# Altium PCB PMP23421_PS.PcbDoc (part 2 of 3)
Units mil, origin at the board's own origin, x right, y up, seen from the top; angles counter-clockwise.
Board outline 1978.53 x 2528.22 mil, 6 copper layers (Top Layer, Signal Layer 1, Signal Layer 2, Signal Layer 3, Signal Layer 4, Bottom Layer), stack 61.3 mil thick; 156 components, 45 nets, 410 pads, 635 vias.
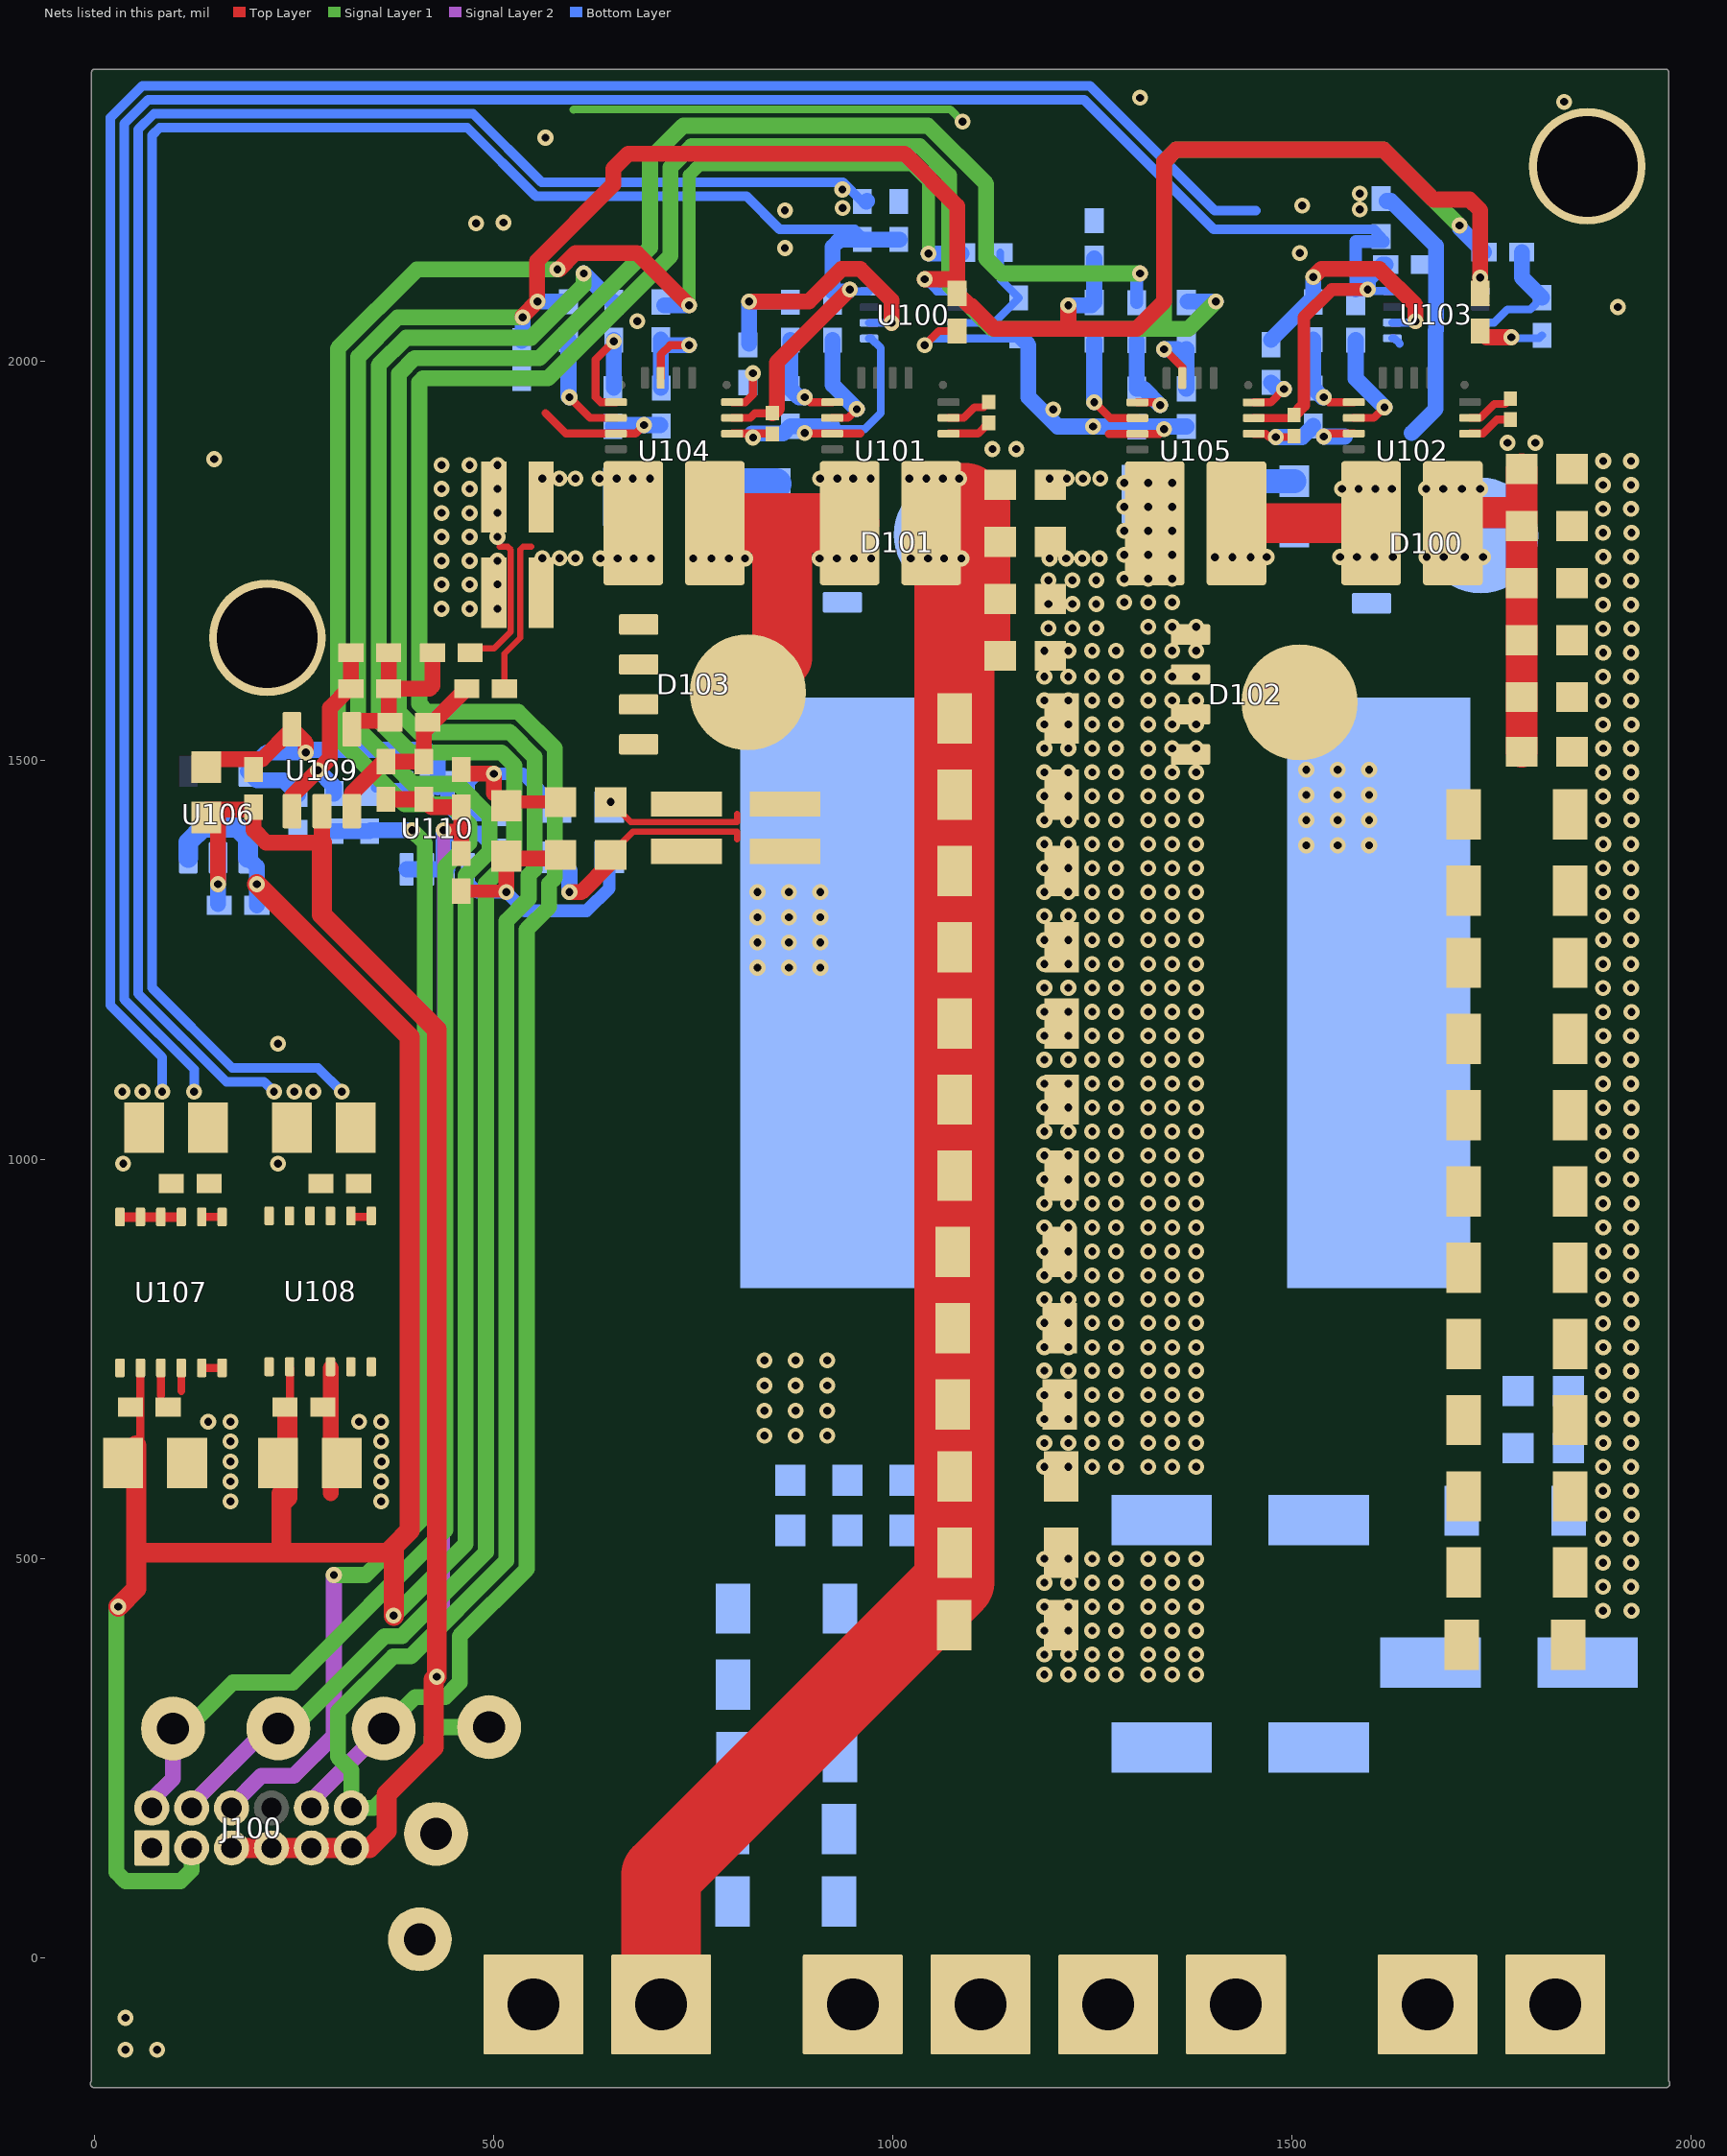
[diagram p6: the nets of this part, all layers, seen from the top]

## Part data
C100 C101 C102 C103 C104 C105 C122 C123 C124 C125 C126 C127 C128 C148 C149 C150 C151 C152 C153 C154 C155 C156 C157 C158 C159 C160 C161 C162 C163 C164 C165: library part C3216X6S1H475K160AB, "CAP CER 4.7UF 100V X7S 1206", Cap_Case=1206, TempCo=X7S, Tolerance_%=10, Value2=100V, ValueDisplayed=4.7µF
C106 C107 C108 C109 C110 C111 C112 C113 C114 C115 C116 C117 C118 C119 C120 C121: library part CMP-0077894-3, "CAP, CERM, 0.22 µF, 100 V,+/- 10%, X7S, AEC-Q200 Grade 1, 0603", Cap_Case=0603, Manufacturer="Taiyo Yuden", Supplier Part Number 1=963-MBASH168SC7224KT, TempCo=X7S, Tolerance_%=10%, Value2=100V, ValueDisplayed=0.22µF
C129 C130 C137 C138 C182 C183: "CAP, CERM, 0.1 µF, 16 V,+/- 10%, X7R, 0402", Cap_Case=0402, Manufacturer=AVX, Supplier Part Number 1=478-7888-1-ND, TempCo=X7R, Tolerance_%=10, Value2=16V, ValueDisplayed=0.1µF
C131 C132 C133 C134 C139 C140 C141 C142: "CAP, CERM, 10pF, 50V, +/-5%, C0G/NP0, 0402", Cap_Case=0402, Manufacturer=MuRata, Supplier Part Number 1=81-GRM1555C1H100JA1D, TempCo=C0G/NP0, Tolerance_%=5, Value1=Unknown, Value2=50V, ValueDisplayed=10pF
C135 C136 C143 C144: library part CMP-0009719-2, "CAP, CERM, 0.1 uF, 25 V, +/- 10%, X5R, 0201", Cap_Case=0201, Manufacturer=MuRata, Supplier Part Number 1=GRM033R61E104KE14D-ND, TempCo=X5R, Tolerance_%=10%, Value1=Unknown, Value2=25V, ValueDisplayed=0.1uF
C145 C146 C147: library part EEE-FK1H220P, "CAP ALUM POLY HYB 22UF 63V SMD", Cap_Case=D, Manufacturer=Rubycon, Tolerance_%=20, Value1="0.88 ohm", Value2=63V, ValueDisplayed=22µF
C166 C167: library part CMP-0006623-2, "CAP, CERM, 0.1 uF, 6.3 V, +/- 10%, X7R, 0402", Cap_Case=0402, Manufacturer=MuRata, Supplier Part Number 1=GRM155R70J104KA01D-ND, TempCo=X7R, Tolerance_%=10%, Value1=Unknown, Value2=6.3V, ValueDisplayed=0.1uF
C168 C176 C192: library part CMP-0064911-2, "CAP, CERM, 10 pF, 50 V,+/- 2.5%, C0G/NP0, AEC-Q200 Grade 1, 0402", Cap_Case=0402, Manufacturer=AVX, Supplier Part Number 1=478-5991-1-ND, TempCo=C0G/NP0, Tolerance_%=2.5%, Value1=Unknown, Value2=50V, ValueDisplayed=10pF
C169 C177: "CAP, CERM, 10 µF, 16 V,+/- 10%, X7S, 0805", Cap_Case=0805, Manufacturer=MuRata, Supplier Part Number 1=490-12756-1-ND, TempCo=X7S, Tolerance_%=10, Value2=16V, ValueDisplayed=10µF
C170 C171 C173 C179: library part 0402ZC103KAT2A, "CAP CER 0.015UF 25V X7R 0402", Cap_Case=0402, Manufacturer=AVX, Supplier Part Number 1=490-17756-1-ND, TempCo=X7R, Tolerance_%=10, Value2=25V, ValueDisplayed=0.015µF
C172 C189: "CAP, CERM, 0.01 µF, 10 V,+/- 10%, X7R, 0402", Cap_Case=0402, Manufacturer=AVX, Supplier Part Number 1=478-7890-1-ND, TempCo=X7R, Tolerance_%=10, Value2=10V, ValueDisplayed=0.01µF
C174 C191: library part CMP-0008377-2, "CAP, CERM, 22 uF, 10 V, +/- 20%, X7R, 0805", Cap_Case=0805, Manufacturer=MuRata, Supplier Part Number 1=81-GRM21BZ71A226ME5L, TempCo=X7R, Tolerance_%=20%, Value1=Unknown, Value2=10V, ValueDisplayed=22uF
C175: library part CMP-0080610-1, "CAP, CERM, 0.1 µF, 25 V,+/- 10%, X7R, AEC-Q200 Grade 1, 0402", Cap_Case=0402, Manufacturer=TDK, Supplier Part Number 1=445-6902-1-ND, TempCo=X7R, Tolerance_%=10%, Value2=25V, ValueDisplayed=0.1µF
C180 C181: library part CMP-0007473-4, "CAP, CERM, 1800 pF, 100 V, +/- 10%, X7R, 0603", Cap_Case=0603, Manufacturer=MuRata, Supplier Part Number 1=490-1477-1-ND, TempCo=X7R, Tolerance_%=10%, Value1=Unknown, Value2=100V, ValueDisplayed=1800pF
C184: "CAP, CERM, 68 pF, 50 V,+/- 5%, C0G/NP0, 0603", Cap_Case=0603, Manufacturer=AVX, Supplier Part Number 1=478-1173-1-ND, TempCo=C0G/NP0, Tolerance_%=5, Value1="0.144 ohm", Value2=50V, ValueDisplayed=68pF
C185 C186: "CAP, CERM, 47 pF, 50 V,+/- 1%, C0G/NP0, 0402", Cap_Case=0402, Manufacturer=MuRata, Supplier Part Number 1=490-6241-1-ND, TempCo=C0G/NP0, Tolerance_%=1, Value2=50V, ValueDisplayed=47pF
C187: "CAP, CERM, 1 µF, 16 V,+/- 10%, X7R, 0603", Cap_Case=0603, Manufacturer=TDK, Supplier Part Number 1=445-1604-1-ND, TempCo=X7R, Tolerance_%=10, Value1="0.0057 ohm", Value2=16V, ValueDisplayed=1µF
C188: "CAP, CERM, 0.1uF, 6.3V, +/-10%, X7R, 0402", Cap_Case=0402, Manufacturer=MuRata, Supplier Part Number 1=GRM155R70J104KA01D-ND, TempCo=X7R, Tolerance_%=10, Value1=Unknown, Value2=6.3V, ValueDisplayed=0.1uF
D100 D101 D102 D103: library part CMP-0032275-1, "Diode 100 V 30A Surface Mount PowerFlat™ (5x6)", Digikey Part Number=497-10342-1-ND, Forward Current=30A, Manufacturer=STMicroelectronics, Max Surge Forward Current=200A, Mouser Part Number=511-STPS30M100DJF-TR, Operating Temperature Range="to +150°C", Peak Reverse Current=100uA
J100: library part CMP-0093439-1, "Connector Header Through Hole, Right Angle 12 position 0.050\" (1.27mm)", Current_A=1A, Digikey Part Number=952-1396-ND, Manufacturer=Harwin, Mouser Part Number=855-M50-3900642, Operating Temperature Range="-40°C to +105°C"
L100: library part CMP-0063542-1, "Inductor, Shielded, 2.2 uH, 48 A, 0.00123 ohm, AEC-Q200 Grade 0, SMD", Manufacturer=Vishay-Dale, Supplier Part Number 1=52X6073, Value1="0.00123 ohm", Value2=48A, ValueDisplayed=2.2uH
LOGO100: library part CMP-0074837-1, "IEC 61010-1 Hot Surface Warning"
Logo101: library part Pb-Free
Logo102: library part CMP-0074769-1
Logo103: library part CMP-0074847-1, "FCC_disclaimer"
R100 R101 R111 R112: "RES, 3.01, 1%, 0.063 W, 0402", Manufacturer=Vishay-Dale, Power_W=0.063, Supplier Part Number 1=541-3.01LLCT-ND, TempCo="100 ppm/C", Tolerance_%=1, Value1=1%, Value2=0.063W, Value_Code=3R01, ValueDisplayed=3.01
R102 R103 R119 R123: library part CMP-0015357-3, "RES, 0.002, 2%, 1 W, 0508", Manufacturer="Susumu Co Ltd", Power_W=1W, Supplier Part Number 1=408-1592-1-ND, TempCo="100 ppm/C", Tolerance_%=2%, Value_Code=2L000, ValueDisplayed=0.002
R104 R105 R106 R107 R108 R109 R113 R114 R117 R118 R124 R128: "RES, 0, 5%, 0.063 W, 0402", Manufacturer=Vishay-Dale, Power_W=0.063, Supplier Part Number 1=541-0.0JCT-ND, TempCo="200 ppm/C", Tolerance_%=5, Value1=5%, Value2=0.063W, Value_Code=0000, ValueDisplayed=0
R110 R120 R121 R122: "RES, 100, 1%, 0.1 W, 0603", Manufacturer="Yageo America", Power_W=0.1, Supplier Part Number 1=311-100HRCT-ND, TempCo="200 ppm/C", Tolerance_%=1, Value1=1%, Value2=0.1W, Value_Code=100R, ValueDisplayed=100
R115 R116: library part CMP-0016888-3, "RES, 2.55, 1%, 0.25 W, AEC-Q200 Grade 0, 1206", Manufacturer=Vishay-Dale, Power_W=250mW, Supplier Part Number 1=541-2.55FFCT-ND, TempCo="100 ppm/C", Tolerance_%=1%, Value2=0.25W, Value_Code=2R55, ValueDisplayed=2.55
R127 R129: "RES, 33.2 k, 1%, 0.063 W, 0402", Manufacturer=Vishay-Dale, Power_W=0.063, Supplier Part Number 1=541-33.2KLCT-ND, TempCo="100 ppm/C", Tolerance_%=1, Value1=1%, Value2=0.063W, Value_Code=33k2, ValueDisplayed=33.2k
R327 R328: library part CMP-0026071-3, "RES, 1.00 k, 1%, 0.063 W, AEC-Q200 Grade 0, 0402", Manufacturer=Vishay-Dale, Power_W=63mW, Supplier Part Number 1=541-1.00KLCT-ND, TempCo="100 ppm/C", Tolerance_%=1%, Value2=0.063W, Value_Code=1k00, ValueDisplayed=1.00k
TP100 TP101 TP102 TP103: "Test Point, Miniature, Orange, TH", Color=Orange, Manufacturer=Keystone, Supplier Part Number 1=36-5003-ND
TP104 TP105: "Test Point, Miniature, Black, TH", Color=Black, Manufacturer=Keystone, Supplier Part Number 1=36-5001-ND
U100 U103: library part CMP-0035039-1, "General Purpose Dual-Channel Functional Isolators", Manufacturer="Texas Instruments", Max Supply Voltage=5.5V, Min Supply Voltage=1.71V, Nominal Supply Current=1.2-5.2mA, Operating Temperature Range="-40°C to +125°C"
U101 U102 U104 U105: library part CMP-0037654-1, "100-V, 64-A GaN with Integrated Driver", Manufacturer="Texas Instruments", Max Supply Voltage=5.25V, Min Supply Voltage=4.75V, Nominal Supply Current=3mA, Operating Temperature Range="-40°C to +125°C"
U106: library part CMP-0066771-1, "150-mA, Low-Dropout Regulator with Foldback Current Limit for Portable Devices, DBV0005A (SOT-23-5)", Alternate Manufacturer="Texas Instruments", Alternate PartNumber=TLV71333PDBVT
U107 U108: library part CMP-0098322-4, "1.5W, High-Density, >3 kVRMS Isolated DC-DC Converter", Manufacturer="Texas Instruments", Max Supply Voltage=5.5V, Min Supply Voltage=4.5V, Operating Temperature Range=to, Output Voltage=5V
U109: library part CMP-0032028-2, "CMOS Amplifier 1 Circuit Rail-to-Rail SOT-23-5", Digikey Part Number=296-TLV365DBVRQ1-ND, Input Bias Current=0.000005uA, Input Offset Voltage=0.4mV, Manufacturer="Texas Instruments", Max Supply Voltage=5.5V, Min Supply Voltage=2.2V, Mouser Part Number=595-TLV365DBVRQ1, Nominal Supply Current=4.6mA, Operating Temperature Range="-40°C to +125°C", Output Current Per Channel=85mA, Voltage Gain=120dB
U110: library part CMP-0093654-2, "-4-V to 110-V, Bidirectional, 1-MHz, 5V/µs, Ultra-Precise Current Sense Amplifier, SOT23-8", Input Bias Current=40uA, Input Offset Voltage=0.002mV, Manufacturer="Texas Instruments", Max Supply Voltage=20V, Min Supply Voltage=2.7V, Nominal Supply Current=2.5mA, Operating Temperature Range="-40°C to +125°C", Voltage Gain=0.05V/mV
VBAT100 VBAT101 VBAT-100 VBAT-101 VBAT-102 VBAT-103 VOUT100 VOUT101: library part CMP-0055044-1, "PCB Pin, 0.04\" DIA, Edge-Mount", Manufacturer=Mill-Max, Supplier Part Number 1=ED1278-ND

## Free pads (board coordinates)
  round 146 hole 125.98: 1(216.54,1653.54) 1(1870.08,2244.09)

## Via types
v1: diameter 20, hole 10, Top Layer to Bottom Layer, 627 vias
v2: diameter 20, hole 10, Top Layer to Bottom Layer, tented both sides, 8 vias

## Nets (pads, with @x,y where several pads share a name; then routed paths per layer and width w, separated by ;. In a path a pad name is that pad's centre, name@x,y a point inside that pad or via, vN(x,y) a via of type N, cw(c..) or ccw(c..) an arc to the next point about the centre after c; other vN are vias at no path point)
3V3: C166.1 C175.1 C187.1 C188.1 U106.5 U109.5 U110.6 U110.7 | length 634
  Top Layer w20: C187.1@140,1501.5 210.16,1501.5 U109.5@247.6,1538.94 265,1521.54 v1(265,1510)
  Bottom Layer w16: 430,1466.01 U110.7@442.33,1466.01 442.33,1443.17 453.66,1431.84 C188.1@514.3,1431.84
  Bottom Layer w20: C166.1@255,1457.24 237.24,1475 203.78,1475 U106.5@192.4,1486.38 216.02,1510 v1(265,1510) 268.26,1513.26 416.74,1513.26 430,1500 430,1466.01
5V: C137.1 C138.1 C167.1 C169.1 C171.1 C177.1 C179.1 C182.1 C183.1 J100.3 R111.1 R112.1 U100.1 U103.1 U106.1 U106.3 U107.1 U107.2 U108.1 U108.2 | length 6582.2
  Top Layer w10: C177.1@57.68,641.9 U107.2@57.68,739.13 ; 245.08,676.38 U108.2@245.08,739.13
  Top Layer w20: v1(536.52,2055) 536.52,2056.52 v1(555,2075) 554.5,2075.5 554.5,2125.56 650,2221.06 650,2241 669,2260 1015,2260 1080.72,2194.28 1080.72,2105 ; v1(1040,2102.71) 1078.43,2102.71 1080.72,2105 ; 1220,2044 v1(1220,2070.06) ; C183.1@1736.05,2085.06 1736.05,2188.95 1722.5,2202.5 1677.5,2202.5 1615,2265 1355,2265 1340,2250 1340,2075 1305.5,2040.5 1127.51,2040.5 1098.95,2069.06 1096.71,2069.06 C182.1@1080.72,2085.06 1080.72,2105
  Top Layer w25: v1(30,440) 52.51,462.51 C177.1@52.51,641.9 ; 60.21,507.7 367.3,507.7 375,515.4 ; v1(203.62,1345) 395,1153.62 395,535.4 375,515.4 ; 234.12,520.88 234.12,569.12 ; 234.12,581.61 234.12,569.12 ; 241.73,676.38 241.73,576.73 234.12,569.12 ; v1(375,428.7) 375,515.4
  Signal Layer 1 w20: v1(30,440) 27.56,437.56 27.56,107.44 38.75,96.25 108.06,96.25 121.85,110.04 J100.3@121.85,137.8 ; v1(375,428.7) 465.07,518.78 465.07,1356.12 495,1386.05 495,1430.56 455.06,1470.5 399.09,1470.5 330.54,1539.05 330.54,2005.53 380.01,2055 v1(536.52,2055)
  Bottom Layer w10: v1(1040,2102.71) 1055.19,2087.52 U100.1@1080.72,2087.52 ; U103.1@1736.05,2087.85 v1@1736.05,2109.43
  Bottom Layer w20: U106.1@192.4,1378.11 203.62,1366.89 v1(203.62,1345) C167.1@203.62,1318.62 ; C137.1@535.09,2025.54 536.52,2026.98 v1(536.52,2055) ; v1(555,2075) R111.1@593.31,2075 ; v1(1220,2070.06) R112.1@1248.95,2070.06 ; R112.1@1252.44,2073.54 C138.1@1252.44,2128.99
  Bottom Layer w25: U106.3@117.6,1378.11 117.6,1397.6 135.8,1415.8 179.2,1415.8 192.4,1402.6 U106.1@192.4,1378.11
  other v1: 1736.05,2105
12V: J100.1 | length 1.8
  Signal Layer 1 w20: J100.1@70.87,136.81 J100.1@71.85,137.8
  Bottom Layer w12: J100.1@71.85,137.8 J100.1@71.85,138.23
48VOUT1: C114.1 C115.1 C116.1 C117.1 C118.1 C119.1 C120.1 C121.1 C122.1 C123.1 C124.1 C125.1 C126.1 C127.1 C128.1 C145.1 C146.1 C147.1 C160.1 C161.1 C162.1 C163.1 C164.1 C165.1 D100.5 U102.7 VOUT100.1 VOUT101.1 | length 423.7
  Top Layer w39.37: U102.7@1701.64,1810.45 C119.1@1771.06,1810.45 ; C115.1@1787.93,1510.75 C117.1@1787.93,1579.15 C121.1@1787.93,1650.63 C120.1@1787.93,1722.11 C119.1@1787.93,1793.58 C118.1@1787.93,1865.06
  other v1: 1668.83,1754.85 1690.19,1754.85 1716.66,1754.85 1739.43,1754.85 1668.27,1840.08 1689.85,1840.08 1712.99,1840.08 1736,1840.08 1770,1897.79 1805,1897.79
CSA: C129.2 C132.2 C143.2 C173.2 C180.1 C189.2 C191.2 D101.1 D101.2 D101.3 D101.4 D103.5 R102.1 R103.1 R120.2 R121.2 U100.5 U101.4 U101.6 U104.7 U104.8 U108.9 U108.10 U108.11 U108.12 | length 3175.6
  Top Layer w7.87: v1(646.83,1447.93) 671.7,1423 804.86,1423 804.86,1432.88
  Top Layer w10: U104.8@798.96,1909.37 C143.2@848.88,1909.37 ; v1@890.63,1909.37 U101.4@924.29,1909.37 959.54,1909.37
  Top Layer w75: U104.7@777.3,1797.17 861.62,1797.17 ; D103.5@861.62,1628.37 861.62,1797.17 ; U101.6@945.94,1797.17 861.62,1797.17
  Bottom Layer w10: 924.66,1918.59 928.25,1915 965,1915 985,1935 985,2016.66 973.19,2028.47 U100.5@970.48,2028.47
  Bottom Layer w12: v1(225,1085) 212.5,1097.5 165.25,1097.5 55,1207.75 55,2290.5 74.7,2310.2 474.25,2310.2 560.03,2224.43 937.32,2224.43 C189.2@961.8,2199.94
  Bottom Layer w20: v1@823.92,1909.37 862.44,1909.37 C132.2@871.65,1918.59 924.66,1918.59 ; C189.2@967.11,2200 C189.2@967.89,2200.79
  other v1: 230,995 250.29,1085 274.26,1085 772.98,1753 815.1,1753 908.52,1753 951.49,1753 909.06,1853 930.55,1853 950.71,1853 972.36,1853 825.15,1904.42 890,1910 865,2141.77 865,2188.98 937.32,2191.85 937.01,2215.07
  other v2: 750.14,1753 795.02,1753 930.2,1753 973.11,1753
CSB: L100.1 R102.2 R103.2 R110.2 R122.2 | length 306.6
  Top Layer w7.87: R122.2@646.83,1382.83 675,1411 804.86,1411 804.86,1401.14
  Top Layer w20: v1(595,1335) 609.98,1335 646.83,1371.85 R122.2@646.83,1381.46
  Bottom Layer w20: R110.2@578.59,1378.5 595,1362.09 v1(595,1335)
  other v1: 830.63,1240.51 870,1240.51 909.37,1240.51 830.63,1272.01 870,1272.01 909.37,1272.01 830.63,1303.5 870,1303.5 909.37,1303.5 830.63,1335 870,1335 909.37,1335
HO1: R108.1 U104.10 | length 56.6
  Top Layer w10: U104.10@798.96,1948.74 815.34,1948.74 825,1958.4 v1(825,1985)
HO2: R109.1 U105.10 | length 64.1
  Top Layer w10: U105.10@1452.29,1948.5 1473.42,1948.5 v1(1490,1965.08)
  Bottom Layer w20: R109.1@1473.97,1973.4 1482.28,1965.08 v1(1490,1965.08)
I_discharge: J100.6 R124.2 R128.2 | length 1481.4
  Signal Layer 2 w10: v1@394.1,1416.37 v1(398.04,1412.43)
  Signal Layer 2 w20: J100.6@171.85,187.8 171.85,190.9 209.3,228.35 249.87,228.35 300,278.48 v1(300,479.7)
  Signal Layer 1 w20: v1(300,479.7) 340,479.7 414.07,553.78 414.07,1396.4 v1(398.04,1412.43)
  Bottom Layer w20: R128.2@300,1411.38 R124.2@345,1411.38 ; R124.2@346.06,1412.43 v1(398.04,1412.43)
NetC131_2: C131.2 R104.2 U100.3 | length 156.8
  Bottom Layer w10: U100.3@1080.72,2048.15 1126.78,2048.15 C131.2@1158.04,2079.41 1134.73,2102.71 R104.2@1134.73,2136.3
NetC132_1: C132.1 R105.2 U101.2 | length 120.5
  Top Layer w10: v1(890,1955) 896.26,1948.74 U101.2@924.29,1948.74
  Bottom Layer w20: R105.2@871.65,2026.6 C132.1@871.65,1965.83 882.48,1955 v1(890,1955)
NetC133_1: C133.1 R106.2 U102.2 | length 118.7
  Top Layer w10: v1(1540,1955) 1546.26,1948.74 U102.2@1577.62,1948.74
  Bottom Layer w20: R106.2@1526.98,2027.02 C133.1@1526.98,1966.25 1538.23,1955 v1(1540,1955)
NetC134_2: C134.2 R107.1 U103.3 | length 157.6
  Bottom Layer w10: U103.3@1736.05,2048.48 1753.48,2048.48 1770,2065 1798.63,2065 C134.2@1813.36,2079.74
  Bottom Layer w20: R107.1@1788.06,2136.62 1788.06,2105.04 C134.2@1813.36,2079.74
NetC135_1: C135.1 U101.9 | length 58.5
  Top Layer w10: U101.9@1069.96,1929.06 1089.14,1929.06 1102.4,1942.32 1113.9,1942.32 C135.1@1120.32,1948.75
NetC135_2: C135.2 U101.8 | length 55.9
  Top Layer w10: U101.8@1069.96,1909.37 1106.93,1909.37 C135.2@1120.32,1922.77
NetC136_1: C136.1 U102.9 | length 60.3
  Top Layer w10: U102.9@1723.29,1929.06 1736.13,1929.06 1753.63,1946.56 1767.23,1946.56 C136.1@1773.66,1952.99
NetC136_2: C136.2 U102.8 | length 57.7
  Top Layer w10: U102.8@1723.29,1909.37 1739.37,1909.37 1757.01,1927.01 C136.2@1773.66,1927.01
NetC139_1: C139.1 R117.2 U104.2 | length 167
  Top Layer w10: v1(650.77,2025) 627.96,2002.19 627.96,1955 634.22,1948.74 U104.2@653.29,1948.74
  Bottom Layer w20: C139.1@650.77,1966.93 v1(650.77,2025) R117.2@650.77,2026.6
NetC140_1: C140.1 R113.2 U104.14 | length 158.2
  Top Layer w10: U104.14@709.39,1979.26 709.39,2008.39 721,2020 v1(745,2020)
  Bottom Layer w20: C140.1@709.52,1966.8 R113.2@709.52,2027.05 ; R113.2@716.57,2020 v1(745,2020)
NetC141_1: C141.1 R114.2 U105.14 | length 111.8
  Top Layer w10: v1(1340,2015) 1340.44,2015 1362.72,1992.72 U105.14@1362.72,1979.01
  Bottom Layer w20: v1(1340,2015) R114.2@1356.66,2015 ; C141.1@1367.9,1965.48 R114.2@1367.9,2015
NetC142_1: C142.1 R118.2 U105.2 | length 128.4
  Top Layer w10: U105.2@1306.62,1948.5 1331.5,1948.5 v1(1335,1945)
  Bottom Layer w20: R118.2@1305.58,2026 C142.1@1305.58,1965.23 1314.77,1965.23 v1(1335,1945)
NetC168_1: C168.1 R127.1 R128.1 U109.1 | length 267.6
  Top Layer w20: U109.1@247.6,1436.57 247.6,1455.35 v1(280,1487.76) 295.09,1502.85 295.09,1565.83 319.26,1590 R127.1@321.38,1590 C168.1@321.38,1635
  Bottom Layer w20: v1(280,1487.76) 300,1467.76 R128.1@300,1458.62
NetC168_2: C168.2 C176.1 R127.2 R327.2 U109.4 | length 219.1
  Top Layer w20: U109.4@332.93,1549.47 368.62,1549.47 R127.2@368.62,1590 ; C168.2@368.62,1635 R127.2@368.62,1590 ; R327.2@423.51,1635 423.51,1593.51 420,1590 R127.2@368.62,1590
NetC176_2: C176.2 C192.1 R129.2 R328.2 U109.3 | length 242.5
  Top Layer w20: U109.3@322.4,1436.57 322.4,1458.65 362.37,1498.62 R129.2@365.4,1498.62 C192.1@412.65,1498.62 412.65,1536.27 R328.2@466.38,1590
NetC180_2: C180.2 R115.2 | length 59.9
  Bottom Layer w39.37: R115.2@793.65,1846.56 C180.2@853.59,1846.56
NetC181_2: C181.2 R116.1 | length 60.8
  Bottom Layer w29.53: R116.1@1442.36,1849.74 C181.2@1503.2,1849.74
NetC184_1: C184.1 C185.1 R110.1 R120.1 U110.8 | length 261.2
  Top Layer w16: C184.1@520.72,1447.87 R120.1@583.84,1447.87
  Top Layer w20: C185.1@464.94,1483.3 v1(500.4,1483.3) C184.1@500.4,1458.9
  Bottom Layer w16: U110.8@467.92,1466.01 467.92,1471.33 479.89,1483.3 v1(500.4,1483.3) 536.79,1483.3 R110.1@578.59,1441.5
NetC184_2: C184.2 C186.1 R121.1 R122.1 U110.1 | length 422.6
  Top Layer w16: C186.1@459.62,1336.38 v1@514.7,1336.38
  Top Layer w20: v1(516.07,1335) C184.2@516.07,1377.28 ; C184.2@516.07,1380.23 C184.2@516.07,1377.28 ; R122.1@579.66,1377.28 C184.2@516.07,1377.28
  Bottom Layer w16: U110.1@467.92,1363.65 467.92,1347.08 480,1335 v1(516.07,1335) 539.57,1311.5 616.5,1311.5 645,1340 R121.1@645,1378.5
NetR100_2: R100.2 U101.3 | length 134.4
  Top Layer w10: U101.3@924.29,1929.06 944.06,1929.06 v1(955,1940)
  Bottom Layer w20: R100.2@924.66,2026.6 924.66,1970.34 v1(955,1940)
NetR101_2: R101.2 U102.3 | length 142.8
  Top Layer w10: U102.3@1577.62,1929.06 1602.7,1929.06 v1(1615.97,1942.32)
  Bottom Layer w20: R101.2@1579.99,2026.38 1579.99,1978.3 v1(1615.97,1942.32)
NetR105_1: R105.1 R108.2 U100.6 | length 371.5
  Top Layer w20: v1(820,2075) 895.25,2075 935.75,2115.5 959.5,2115.5 998.65,2076.35 v1(998.65,2048.15)
  Bottom Layer w10: U100.6@970.48,2048.15 v1(998.65,2048.15)
  Bottom Layer w20: R108.2@820,2021.95 v1(820,2075) R105.1@870.49,2075
NetR106_1: R106.1 R109.2 U103.6 | length 302.7
  Top Layer w20: v1(1526.98,2105.58) 1536.91,2115.5 1609.56,2115.5 1655,2070.06 v1(1655,2050)
  Bottom Layer w10: U103.6@1625.81,2048.48 v1@1653.48,2048.48
  Bottom Layer w20: R109.2@1473.97,2026.81 1521.43,2074.26 R106.1@1526.98,2074.26 v1(1526.98,2105.58)
NetR111_2: R111.2 U104.3 | length 141.6
  Top Layer w10: v1(595,1955) 620.94,1929.06 U104.3@653.29,1929.06
  Bottom Layer w20: R111.2@593.91,2027.15 593.91,1956.09 v1(595,1955)
NetR112_2: R112.2 U105.3 | length 140
  Top Layer w10: v1(1252.44,1948.75) 1272.37,1928.82 U105.3@1306.62,1928.82
  Bottom Layer w20: v1(1252.44,1948.75) R112.2@1252.44,2026.3
NetR124_1: R124.1 U110.5 | length 38.8
  Bottom Layer w12: R124.1@352.39,1466.01 U110.5@391.15,1466.01
PWM_BAT_H: J100.2 R104.1 R113.1 TP103.1 | length 3336.7
  Top Layer w20: TP103.1@98.43,267.72 TP103.1@98.43,287.4 ; v1(580,2115) 581.94,2115 602.44,2135.5 679.5,2135.5 v1(745,2070)
  Signal Layer 2 w20: J100.2@71.85,187.8 71.85,197.83 98.43,224.41 TP103.1@98.43,287.4
  Signal Layer 1 w16: v1(745,2070) 745,2233.06 757.94,2246 1024,2246 1045,2225 v1(1045,2135)
  Signal Layer 1 w20: TP103.1@98.43,300.2 TP103.1@98.43,287.4 115.88,287.4 173.48,345 248.66,345 439.57,535.91 439.57,1366.69 469.5,1396.61 469.5,1420 444.5,1445 388.53,1445 305.04,1528.49 305.04,2016.09 403.95,2115 v1(580,2115)
  Bottom Layer w20: R113.1@713.81,2070 v1(745,2070) ; v1(1045,2135) R104.1@1086.19,2135
PWM_BAT_L: J100.4 R117.1 TP102.1 | length 2508.8
  Signal Layer 2 w20: J100.4@121.85,187.8 121.85,192.72 216.54,287.4 TP102.1@230.44,287.4
  Signal Layer 1 w20: TP102.1@230.44,287.4 247.89,287.4 363.69,403.2 385.56,403.2 490.57,508.21 490.57,1345.56 525.9,1380.89 525.9,1493.86 509.76,1510 395.65,1510 356.04,1549.62 356.04,1994.96 390.57,2029.5 547.08,2029.5 613,2095.42 v1(613,2110)
  Bottom Layer w20: v1(613,2110) 649.16,2073.84 R117.1@650.77,2073.84
PWM_BUS_H: J100.10 R107.2 R114.1 TP101.1 | length 4163.7
  Top Layer w20: J100.10@271.85,187.8 J100.10@271.85,190.9
  Signal Layer 2 w20: J100.10@271.85,187.8 271.85,196.81 TP101.1@362.45,287.4 TP101.1@365.44,287.4
  Signal Layer 1 w20: J100.10@271.85,187.8 J100.10@271.85,191.85 ; TP101.1@362.45,287.4 401.75,326.7 439.41,326.7 457.71,345 457.71,403.22 541.57,487.09 541.57,1288.38 569.5,1316.3 569.5,1345.56 576.9,1352.96 576.9,1514.99 530.89,1561 416.78,1561 407.04,1570.74 407.04,1973.84 411.7,1978.5 568.21,1978.5 721.5,2131.79 721.5,2242.79 748.21,2269.5 1033.73,2269.5 1070.5,2232.73 1070.5,2095.27 1125.27,2040.5 1340,2040.5 ; v1(1405,2075) 1370.5,2040.5 1340,2040.5 ; v1(1710,2170) 1615,2265 1355,2265 1340,2250 1340,2040.5
  Bottom Layer w20: R114.1@1369.42,2075 v1(1405,2075) ; v1(1710,2170) 1710,2167.44 R107.2@1740.82,2136.62
PWM_BUS_L: J100.12 R118.1 TP100.1 | length 3573.5
  Signal Layer 2 w16: TP100.1@494.46,289.13 TP100.1@496.06,289.13
  Signal Layer 1 w20: TP100.1@494.46,289.13 434.95,289.13 422.66,276.84 422.66,260.46 350,187.8 J100.12@321.85,187.8 321.85,235.24 305,252.09 305,308.45 374.26,377.7 396.12,377.7 516.07,497.65 516.07,1298.94 544,1326.86 544,1356.12 551.4,1363.53 551.4,1504.42 520.33,1535.5 406.21,1535.5 381.54,1560.18 381.54,1984.4 401.13,2004 557.65,2004 696,2142.35 696,2253.36 737.64,2295 1044.3,2295 1117.2,2222.1 1117.2,2128.8 1136,2110 v1(1310,2110)
  Bottom Layer w16: R118.1@1305.58,2073.24 1305.58,2105.58 v1(1310,2110)
SGND: C114.2 C115.2 C116.2 C117.2 C118.2 C119.2 C120.2 C121.2 C122.2 C123.2 C124.2 C125.2 C126.2 C127.2 C128.2 C131.1 C134.1 C137.2 C138.2 C139.2 C140.2 C141.2 C142.2 C145.2 C146.2 C147.2 C160.2 C161.2 C162.2 C163.2 C164.2 C165.2 C166.2 C167.2 C169.2 C171.2 C175.2 C177.2 C179.2 C182.2 C183.2 C185.2 C186.2 C187.2 C188.2 C192.2 D102.1 D102.2 D102.3 D102.4 D103.1 D103.2 D103.3 D103.4 J100.5 J100.7 J100.9 J100.11 pad.1 R115.1 R116.2 R119.2 R123.2 R129.1 R328.1 TP104.1 TP105.1 U100.4 U103.4 U104.4 U104.6 U105.4 U105.6 U106.2 U107.3 U107.4 U107.5 U107.6 U108.3 U108.4 U108.5 U108.6 U109.2 U110.2 U110.3 U110.4 VBAT-101.1 VBAT-103.1 | length 5138.5
  Top Layer w7.87: R328.1@513.62,1590 513.62,1633.62 533.46,1653.46 533.46,1764.18 537,1767.72 547.38,1767.72
  Top Layer w10: 83.27,704.89 U107.3@83.27,739.13 ; 108.86,710.04 U107.4@108.86,739.13 ; U107.5@134.45,739.13 U107.6@160.04,739.13 ; 565,1935 590.63,1909.37 U104.4@653.29,1909.37 677.76,1909.37 v1(688.39,1920) ; v1(1040,2020) 1057.81,2037.81 C182.2@1080.72,2037.81 ; 1270.87,1909.13 U105.4@1306.62,1909.13 v1@1334.57,1909.13 ; U105.6@1346.09,1760 U105.6@1351.09,1755 ; U105.6@1347.01,1731.04 U105.6@1350.52,1727.54
  Top Layer w16: v1(437.41,1412.43) 459.55,1412.43
  Top Layer w20: C187.2@140,1438.5 C175.2@196.46,1438.5 ; v1(155,1345) C187.2@155,1428.5 ; C175.2@199.43,1441.47 199.43,1412.65 215,1397.07 285,1397.07 U109.2@285,1436.57 ; 296.26,582.47 U108.4@296.26,739.13 ; R129.1@365.4,1451.38 C192.2@412.65,1451.38 422.65,1441.38 C185.2@459.62,1441.38 C186.2@459.62,1383.62 ; C183.2@1736.05,2037.81 1743.86,2030 v1(1775,2030)
  Top Layer w25: J100.5@171.85,137.8 J100.7@221.85,137.8 J100.9@271.85,137.8 J100.11@321.85,137.8 344.86,137.8 366.14,159.08 366.14,204.88 425.2,263.94 v1@425.2,348.55 ; 285,1397.07 285,1306.76 428.85,1162.91 v1(428.85,352.2)
  Signal Layer 2 w16: v1(428.85,352.2) 428.85,410.56 437.41,419.12 v1(437.41,1412.43)
  Signal Layer 2 w20: J100.11@321.85,137.8 J100.11@334.65,137.8
  Signal Layer 1 w10: 600,2315 600.5,2315.5 1071.99,2315.5 v1(1087.49,2300)
  Signal Layer 1 w20: J100.11@321.85,137.8 J100.11@327.07,137.8
  Bottom Layer w10: v1(1040,2020) 1048.47,2028.47 U100.4@1080.72,2028.47 1154.34,2028.47 C131.1@1158.04,2032.16 ; U103.4@1736.05,2028.8 1809.67,2028.8 C134.1@1813.36,2032.49
  Bottom Layer w12: J100.11@321.85,137.8 J100.11@321.85,152.75
  Bottom Layer w20: C167.2@155,1320 v1(155,1345) U106.2@155,1378.11 ; U110.4@391.15,1363.65 U110.3@416.74,1363.65 U110.2@442.33,1363.65 ; U110.2@437.41,1368.57 v1(437.41,1412.43) 441.5,1408.34 484.26,1408.34 506.23,1386.38 C188.2@516.07,1386.38 ; C139.2@649.62,1918.53 651.09,1920 v1(688.39,1920) C140.2@709.08,1920 ; C131.1@1158.04,2032.16 1170,2020.2 1170,1955 1206.71,1918.29 C141.2@1367.85,1918.29
  other v1: 38.75,-115 78.53,-115 38.75,-75 1320,355 1350,355 1380,355 1320,380 1350,380 1380,380 1320,410 1350,410 1380,410 1889.81,435 1925.48,435 1320,440 1350,440 1380,440 1889.81,465 1925,465 1320,470 1350,470 1380,470 1889.81,495 1925,495 1320,500 1350,500 1380,500 1890,525 1925,525 1889.81,555 1925.48,555 170.36,571.85 359.38,571.85 1889.81,585 1925,585 170.36,596.85 359.38,596.85 1320,615 1350,615 1380,615 1889.81,615 1925,615 170.71,621.85 359.73,621.85 1320,645 1350,645 1380,645 1890,645 1925,645 170.36,646.85 359.38,646.85 142.6,671.85 170.36,671.85 331.62,671.85 359.38,671.85 1320,675 1350,675 1380,675 1889.81,675 1925.48,675 1320,705.1 1350,705.1 1380,705.1 1889.81,705 1925,705 1889.81,735 1925,735 1320,735.59 1350,735.59 1380,735.59 1320,765 1350,765 1380,765 1890,765 1925,765 1320,795.39 1350,795.39 1380,795.39 1889.81,795 1925.48,795 1320,825 1350,825 1380,825 1889.81,825 1925,825 1320,855 1350,855 1380,855 1889.81,855 1925,855 1320,885 1350,885 1380,885 1890,885 1925,885 1320,915 1350,915 1380,915 1890,915 1925,915 1320,945.11 1350,945.11 1380,945.11 1889.81,945 1925.48,945 1320,975.11 1350,975.11 1380,975.11 1889.81,975 1925,975 1320,1005.11 1350,1005.11 1380,1005.11 1889.81,1005 1925,1005 1320,1035.11 1350,1035.11 1380,1035.11 1890,1035 1925,1035 1320,1065.11 1350,1065.11 1380,1065.11 1889.81,1065 1925.48,1065 1320,1095.11 1350,1095.11 1380,1095.11 1889.81,1095 1925,1095 1320,1125.11 1350,1125.11 1380,1125.11 1889.81,1125 1925,1125 230,1145 1320,1155.11 1350,1155.11 1380,1155.11 1890,1155 1925,1155 1320,1185.11 1350,1185.11 1380,1185.11 1889.81,1185 1925.48,1185 1320,1215.11 1350,1215.11 1380,1215.11 1889.81,1215 1925,1215 1320,1245.11 1350,1245.11 1380,1245.11 1889.81,1245 1925,1245 1320,1275.11 1350,1275.11 1380,1275.11 1890,1275 1925,1275 1320,1305.11 1350,1305.11 1380,1305.11 1889.81,1305 1925.48,1305 1320,1335.11 1350,1335.11 1380,1335.11 1889.81,1335 1925,1335 1320,1365.11 1350,1365.11 1380,1365.11 1889.81,1365 1925,1365 1320,1395.11 1350,1395.11 1380,1395.11 1890,1395 1925,1395 1320,1425.11 1350,1425.11 1380,1425.11 1889.81,1425 1925.48,1425 1320,1455.11 1350,1455.11 1380,1455.11 1889.81,1455 1925,1455 1320,1485.11 1350,1485.11 1380,1485.11 1889.81,1485 1925,1485 1320,1515.11 1350,1515.11 1380,1515.11 1890,1515 1925,1515 1320,1545.11 1350,1545.11 1380,1545.11 1889.81,1545 1925.48,1545 1320,1575.11 1350,1575.11 1380,1575.11 1889.81,1575 1925,1575 1320,1605 1350,1605 1380,1605 1889.81,1605 1925,1605 1890,1635 1925,1635 1320,1637.24 1350,1637.24 1380,1637.24 1889.81,1665 1925.48,1665 1320,1667.47 1350,1667.47 1380,1667.47 1889.81,1695 1925,1695 1290,1697.94 1320,1697.94 1350,1697.94 1889.81,1725 1925,1725 1290,1727.47 1320,1727.47 1350,1727.47 561.13,1753.31 582.62,1753.31 602.78,1753.31 633.93,1753 655.43,1753 675.58,1753 697.23,1753 1890,1755 1925,1755 1290,1757.47 1320,1757.47 1350,1757.47 1889.81,1785 1925.48,1785 1290,1787.47 1320,1787.47 1350,1787.47 1889.81,1815 1925,1815 1290,1817.55 1320,1817.55 1350,1817.55 1889.81,1845 1925,1845 1290,1847.55 1320,1847.55 1350,1847.55 561.03,1852.93 582.52,1852.93 602.67,1852.93 632.8,1853 654.3,1853 674.45,1853 696.1,1853 1890,1875 1925,1875 150,1877.39 1340,1914.91 1250.89,1918.29 1201.16,1939.73 680,2050 1908.5,2067.93 478.08,2172.78 512.31,2173.62 565,2280 1841.07,2325 1310,2330
SW2: C130.2 C133.2 C144.2 C170.2 C172.2 C174.2 C181.1 D100.1 D100.2 D100.3 D100.4 D102.5 L100.2 U102.4 U102.6 U103.5 U105.7 U105.8 U107.9 U107.10 U107.11 U107.12 | length 3509
  Top Layer w10: U105.8@1452.29,1909.13 1467.14,1909.13 1471.27,1905 v1(1480,1905) C144.2@1501.17,1905 ; v1@1543.7,1909.37 U102.4@1577.62,1909.37
  Top Layer w12: U107.12@32.09,928.11 U107.11@57.68,928.11 U107.10@83.27,928.11 101.16,928.11
  Top Layer w50: U105.7@1430.88,1797.17 U102.6@1599.28,1797.17
  Bottom Layer w10: U103.5@1625.81,2028.8 1628.16,2028.8 1635,2021.95
  Bottom Layer w12: v1(85,1085) 85,1128.25 20,1193.25 20,2305 60.2,2345.2 1246.9,2345.2 1403.13,2188.98 1455,2188.98
  Bottom Layer w20: v1(1480,1905) 1512.97,1905 C133.2@1526.98,1919.01 ; v1(1540,1905.68) 1566.66,1905.68 ; C172.2@1618.66,2200.79 1624.21,2200.79 1680.5,2144.5 1680.5,2038.94 1680,2038.44 1680,1940 1650,1910
  other v1: 36.13,995 35,1085 60.21,1085 1518.07,1393.7 1557.44,1393.7 1596.81,1393.7 1518.07,1425.2 1557.44,1425.2 1596.81,1425.2 1518.07,1456.69 1557.44,1456.69 1596.81,1456.69 1518.07,1488.19 1557.44,1488.19 1596.81,1488.19 1425.58,1754.6 1468.43,1754.85 1560.63,1754.85 1603.48,1754.85 1562.95,1840.08 1583.53,1840.08 1604.61,1840.08 1625.26,1840.08 1510,2135.39 1585,2190 1512.97,2195 1585,2210
  other v2: 1403.47,1754.6 1448.35,1754.6 1581.56,1754.85 1626.44,1754.85
VBAT1: C100.1 C101.1 C102.1 C103.1 C104.1 C105.1 C106.1 C107.1 C108.1 C109.1 C110.1 C111.1 C112.1 C113.1 C148.1 C149.1 C150.1 C151.1 C152.1 C153.1 C154.1 C155.1 C156.1 C157.1 C158.1 C159.1 D101.5 U101.7 VBAT100.1 VBAT101.1 | length 2319.3
  Top Layer w25: U101.7@1048.31,1797.17 1077.37,1797.17 1129.89,1797.17 ; C113.1@1134.59,1630.81 C112.1@1134.59,1702.29 C111.1@1134.59,1773.76 1134.59,1822.83
  Top Layer w100: VBAT101.1@710,-58.27 710,103.7 1077.37,471.08 C158.1@1077.37,507.51 C157.1@1077.37,602.96 1077.37,1552.39 1077.37,1797.17 1077.37,1821.47 1078.74,1822.83 1090.55,1822.83
  other v1: 839.21,654.09 878.58,654.09 917.95,654.09 839.21,685.59 878.58,685.59 917.95,685.59 839.21,717.09 878.58,717.09 917.95,717.09 839.21,748.58 878.58,748.58 917.95,748.58 1022.8,1753 1044.3,1753 1064.45,1753 1086.1,1753 1020.75,1853 1042.19,1853 1063.07,1853 1083.44,1853 1125,1890 1155,1890
VBAT-: C100.2 C101.2 C102.2 C103.2 C104.2 C105.2 C106.2 C107.2 C108.2 C109.2 C110.2 C111.2 C112.2 C113.2 C148.2 C149.2 C150.2 C151.2 C152.2 C153.2 C154.2 C155.2 C156.2 C157.2 C158.2 C159.2 R119.1 R123.1 R327.1 VBAT-100.1 VBAT-102.1 | length 183.4
  Top Layer w7.87: R327.1@470.71,1640.16 500.4,1640.16 521.65,1661.42 521.65,1763.78 517.72,1767.72 507.87,1767.72 ; v1(505,1780) v1@509.13,1775.87
  other v1: 1190,355 1220,355 1250,355 1280,355 1190,380 1220,380 1250,380 1280,380 1190,410 1220,410 1250,410 1280,410 1190,440 1220,440 1250,440 1280,440 1190,470 1220,470 1250,470 1280,470 1190,500 1220,500 1250,500 1280,500 1190,615 1220,615 1250,615 1280,615 1190,645 1220,645 1250,645 1280,645 1190,675 1220,675 1250,675 1280,675 1190,705.1 1220,705.1 1250,705.1 1280,705.1 1190,735.59 1220,735.59 1250,735.59 1280,735.59 1190,765 1220,765 1250,765 1280,765 1190,795.39 1220,795.39 1250,795.39 1280,795.39 1190,825 1220,825 1250,825 1280,825 1190,855 1220,855 1250,855 1280,855 1190,885 1220,885 1250,885 1280,885 1190,915 1220,915 1250,915 1280,915 1190,945.11 1220,945.11 1250,945.11 1280,945.11 1190,975.11 1220,975.11 1250,975.11 1280,975.11 1190,1005.11 1220,1005.11 1250,1005.11 1280,1005.11 1190,1035.11 1220,1035.11 1250,1035.11 1280,1035.11 1190,1065.11 1220,1065.11 1250,1065.11 1280,1065.11 1190,1095.11 1220,1095.11 1250,1095.11 1280,1095.11 1190,1125.11 1220,1125.11 1250,1125.11 1280,1125.11 1190,1155.11 1220,1155.11 1250,1155.11 1280,1155.11 1190,1185.11 1220,1185.11 1250,1185.11 1280,1185.11 1190,1215.11 1220,1215.11 1250,1215.11 1280,1215.11 1190,1245.11 1220,1245.11 1250,1245.11 1280,1245.11 1190,1275.11 1220,1275.11 1250,1275.11 1280,1275.11 1190,1305.11 1220,1305.11 1250,1305.11 1280,1305.11 1190,1335.11 1220,1335.11 1250,1335.11 1280,1335.11 1190,1365.11 1220,1365.11 1250,1365.11 1280,1365.11 1190,1395.11 1220,1395.11 1250,1395.11 1280,1395.11 1190,1425.11 1220,1425.11 1250,1425.11 1280,1425.11 1190,1455.11 1220,1455.11 1250,1455.11 1280,1455.11 1190,1485.11 1220,1485.11 1250,1485.11 1280,1485.11 1190,1515.11 1220,1515.11 1250,1515.11 1280,1515.11 1190,1545.11 1220,1545.11 1250,1545.11 1280,1545.11 1190,1575.11 1220,1575.11 1250,1575.11 1280,1575.11 1190,1605 1220,1605 1250,1605 1280,1605 1190,1637.24 1220,1637.24 1250,1637.24 1280,1637.24 1195,1665.5 1225,1665.5 1255,1665.5 435,1690 470.04,1690 505,1690 1195,1695.97 1225,1695.97 1255,1695.97 435,1720.47 470.04,1720.47 505,1720.47 1195,1725.5 1225,1725.5 1255,1725.5 435,1750 470.04,1750 505,1750 1196.64,1753 1217.26,1753 1237.41,1753 1259.06,1753 435,1780 470.04,1780 435,1810 470.04,1810 505,1810 435,1840.08 470.04,1840.08 505,1840.08 1196.64,1852.93 1218.13,1852.93 1238.28,1852.93 1259.94,1852.93 435,1870.08 470,1870.08 505,1870
VDD_1H_D: C129.1 C143.1 C173.1 C189.1 C191.1 R100.1 U100.8 U104.9 U108.7 U108.8 | length 2776.7
  Top Layer w10: U108.8@321.85,928.11 U108.7@347.44,928.11 ; U104.9@798.96,1929.06 821.6,1929.06 827.46,1934.92 C143.1@849.32,1934.92
  Top Layer w20: C143.1@849.32,1934.92 855,1940.6 855,1998.69 v1(946.31,2090)
  Bottom Layer w10: v1@946.31,2087.52 U100.8@970.48,2087.52
  Bottom Layer w12: v1(310,1085) 280,1115 172.5,1115 72.5,1215 72.5,2283.25 81.95,2292.7 467,2292.7 552.78,2206.93 816.64,2206.93 858.57,2165 952.5,2165 965.02,2152.48 C189.1@965.93,2151.57
  Bottom Layer w20: v1(946.31,2090) 943.84,2087.52 924.66,2087.52 924.66,2143.35 934.01,2152.7 C189.1@961.8,2152.7 ; C189.1@965.02,2152.48 1008.79,2152.48 C129.1@1008.92,2152.34
VDD_2H_D: C130.1 C144.1 C170.1 C172.1 C174.1 R101.1 U103.8 U105.9 U107.7 U107.8 | length 3385.2
  Top Layer w10: U107.8@134.45,928.11 U107.7@160.04,928.11 ; U105.9@1452.29,1928.82 C144.1@1499.01,1928.82
  Top Layer w16: C144.1@1502.65,1932.46 1515,1944.81 1515,2055 1550,2090 v1(1595,2090)
  Bottom Layer w10: v1@1595,2087.85 U103.8@1625.81,2087.85
  Bottom Layer w12: v1(125,1085) 125,1113 37.5,1200.5 37.5,2297.75 67.45,2327.7 1239.65,2327.7 1402.36,2165 1603.18,2165 C172.1@1611.8,2156.38
  Bottom Layer w16: R101.1@1579.99,2088.08 1581.14,2089.23 1594.23,2089.23 v1(1595,2090) ; 1579.99,2090 1579.99,2149.76 C172.1@1614.89,2149.77
  Bottom Layer w20: v1(1595,2090) 1595,2102.4 1613.72,2121.12 C130.1@1617.66,2121.12
pads on no net: J100.8 U100.2 U100.7 U101.1 U101.5 U101.10 U101.11 U101.12 U101.13 U101.14 U101.15 U102.1 U102.5 U102.10 U102.11 U102.12 U102.13 U102.14 U102.15 U103.2 U103.7 U104.1 U104.5 U104.11 U104.12 U104.13 U104.15 U105.1 U105.5 U105.11 U105.12 U105.13 U105.15 U106.4

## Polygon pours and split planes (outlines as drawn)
48VOUT1 on Bottom Layer "48Vout1" (solid, remove dead copper, pour order 96): 1755,1910 1730,1885 1665,1885 1655,1875 1655,1680 1660,1675 1832.73,1675 1839.05,1681.32 1839.05,1884.31 1813.36,1910
SW2 on Bottom Layer "SW2" (solid, remove dead copper, pour order 94): 1633.86,1681.14 1725,1590 1725,1425 1678.94,1378.94 1507.87,1378.94 1429.13,1457.68 1429.13,1685.04 1393.7,1720.47 1393.7,1770 1411.33,1786.33 1460,1786.33 1490,1816.33 1490,1818.24 1521.9,1818.24 1531.74,1828.09 1531.74,1864.69 1545,1877.95 1625.98,1877.95 1633.86,1870.08
VBAT1 on Bottom Layer "VBAT1" (solid, remove dead copper, pour order 92): 1109.73,1900 1047.17,1900 1005,1857.83 1005,1691.32 1015,1681.32 1169.62,1681.32 1175,1686.7 1175,1889.16 1164.16,1900
VBAT1 on Bottom Layer "VBAT1" (solid, remove dead copper, pour order 70): 818.9,-15 870,36.1 870,441.98 830,481.98 830,545 851.93,566.93 1101.93,566.93 1115,580 1115,768.33 1063.33,820 660,820 605,765 605,325 472.44,192.44 472.44,-118.11 496.06,-141.73 795.28,-141.73 818.9,-118.11
CSA on Bottom Layer "CSA" (solid, remove dead copper, pour order 90): 740,1780 748.25,1788.25 808.14,1788.25 844.89,1825 875,1825 890,1840 890,1865 900,1875 980,1875 985,1870 985,1691.32 975,1681.32 798.68,1681.32 740,1740
SGND on Bottom Layer "SGND" (solid, remove dead copper, pour order 100): 1955,350 1940,335 1810,335 1805,340 1805,502.76 1825,522.76 1825,729.21 1870.6,774.81 1870.6,1880.16 1880.44,1890 1945,1890 1955,1880
48VOUT1 on Bottom Layer "48Vout1" (solid, remove dead copper, pour order 104): 1655,1875 1655,1670 1730,1595 1730,835 1720,825 1645,825 1470,650 1470,230 1599.88,100.12 1599.88,-134.88 1610,-145 1945,-145 1955,-135 1955,1768.36 1838.36,1885 1795,1885 1785,1875
CSA on Bottom Layer "CSA" (solid, remove dead copper, pour order 106): 785.3,2230.27 775,2220 775,2218.46 775,2137.39 775,1934.86 818.27,1892.4 975.99,1892.4 1025,1941.41 1025,2027.49 1040,2042.49 1040,2075.46 1025,2090.46 1025,2205 1000,2230
SW2 on Bottom Layer "SW2" (solid, remove dead copper, pour order 120): 1425,2200 1445,2220 1625,2220 1690,2155 1690,1914.91 1670.09,1895 1445,1895 1425,1915
SGND on Bottom Layer "SGND" (solid, remove dead copper, pour order 154): 694.7,2125.08 694.7,2021.98 566.5,1893.78 421.06,1893.78 414.92,1887.64 414.92,1608.35 454.92,1568.35 541.57,1568.35 589.92,1520 589.92,1315.47 558.54,1284.1 558.54,482.63 470.67,394.75 470.67,-125 450.67,-145 29.92,-145 9.92,-125 9.92,739.42 20.58,750.09 359.91,750.09 374.92,765.1 374.92,1050.22 298.06,1127.08 204.28,1127.07 84.92,1246.44 84.92,1840.5 564.92,2320.5 1229.92,2320.5 1264.92,2355.5 1934.92,2355.5 1959.92,2330.5 1959.92,2020.5 1939.34,1999.92 1705.5,1999.92 1694.92,2010.5 1694.92,2165.81 1605.23,2255.5 1367.02,2255.5 1344.72,2233.19 1344.72,2140.54 1384.92,2100.35 1384.92,1913.45 1366.96,1895.5 1178.47,1895.5 1169.92,1904.05 1169.92,1928.3 1097.72,2000.5 1039.92,2000.5 1029.92,2010.49 1029.92,2210.49 999.92,2240.5 714,2240.5 699,2225.5 699,2129.39
VBAT- on Bottom Layer "VBAT-" (solid, remove dead copper, pour order 172): 878.68,446.99 850,475.67 850,550 866.93,566.93 879.31,567.62 955.11,643.42 955.11,755 935.79,774.32 935.79,1455.86 811.65,1580 565.11,1580 440.11,1580 420.11,1600 420.11,1875 435.11,1890 1240.11,1890 1270.11,1860 1270.11,1665 1300.11,1635 1300.11,210 1190.11,100 1190.11,-120 1168,-142.1 890.11,-142.1 878.68,-130.68
SGND on Bottom Layer "SGND" (solid, remove dead copper, pour order 174): 1280,1860.3 1310,1890 1945,1890 1955,1880 1955,365 1535,-55 1535,-120 1510,-145 1230,-145 1205,-120 1205,100 1310,205 1310,1640 1280,1670
SW2 on Bottom Layer "SW2" (solid, remove dead copper, pour order 186): 25,915 20,920 20,1085 30,1095 90,1095 95,1090 95,1075 100,1070 165,1070 175.19,1059.81 174.97,919.97 170,915
CSA on Bottom Layer "CSA" (solid, remove dead copper, pour order 192): 215,914.39 210,919.39 210,1084.39 220,1094.39 280,1094.39 285,1089.39 285,1074.39 290,1069.39 355,1069.39 365.19,1059.21 364.97,919.36 360,914.39
VDD_1H_D on Top Layer "VDD_1H_D" (solid, remove dead copper, pour order 152): 300,1095 295,1090 295,1015 310,1000 310,920 315,915 355,915 355,915.1 360,920.1 360,1090 355,1095
CSA on Top Layer "CSA" (solid, remove dead copper, pour order 182): 245,980 245,979.87 250,974.87 250,965.11 245.08,960 220.36,960 210.36,950 210.36,920 215.36,915 300.36,915 305.45,920.1 305.45,991.56 285.36,1011.65 285.36,1090 280.36,1095 220.36,1095 210.36,1085 210.36,990 220.36,980
SGND on Top Layer "SGND" (solid, remove dead copper, pour order 134): 523.84,1977.04 573.84,1977.04 574.22,1977.42 574.22,1966.5 605.8,1934.92 696.13,1934.92 715.94,1915.11 715.94,1894.39 715,1893.45 524.65,1893.45 523.84,1892.64
SGND on Top Layer "SGND" (solid, remove dead copper, pour order 88): 1835,1889.45 1825,1879.45 1825,355 1840,340 1945,340 1960,355 1960,1879.69 1950,1889.69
